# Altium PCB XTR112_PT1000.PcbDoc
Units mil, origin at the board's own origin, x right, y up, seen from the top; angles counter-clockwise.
Board outline 2104 x 1160 mil, 2 copper layers (Top Layer, Bottom Layer); 29 components, 24 nets, 75 pads, 33 vias.
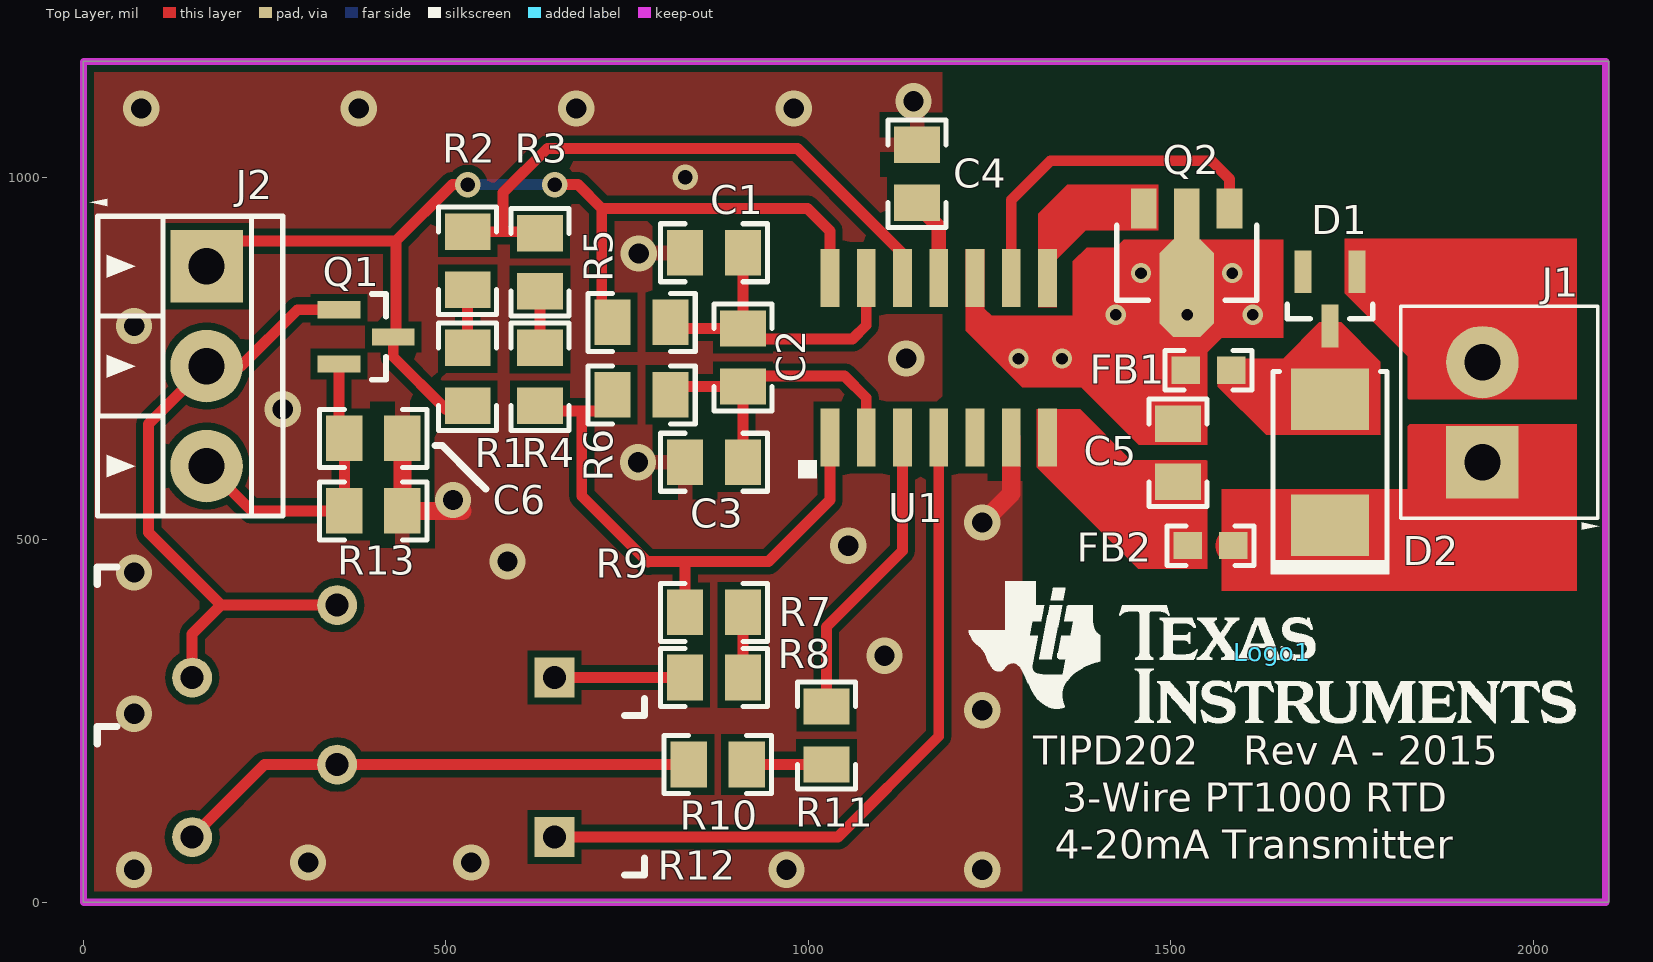
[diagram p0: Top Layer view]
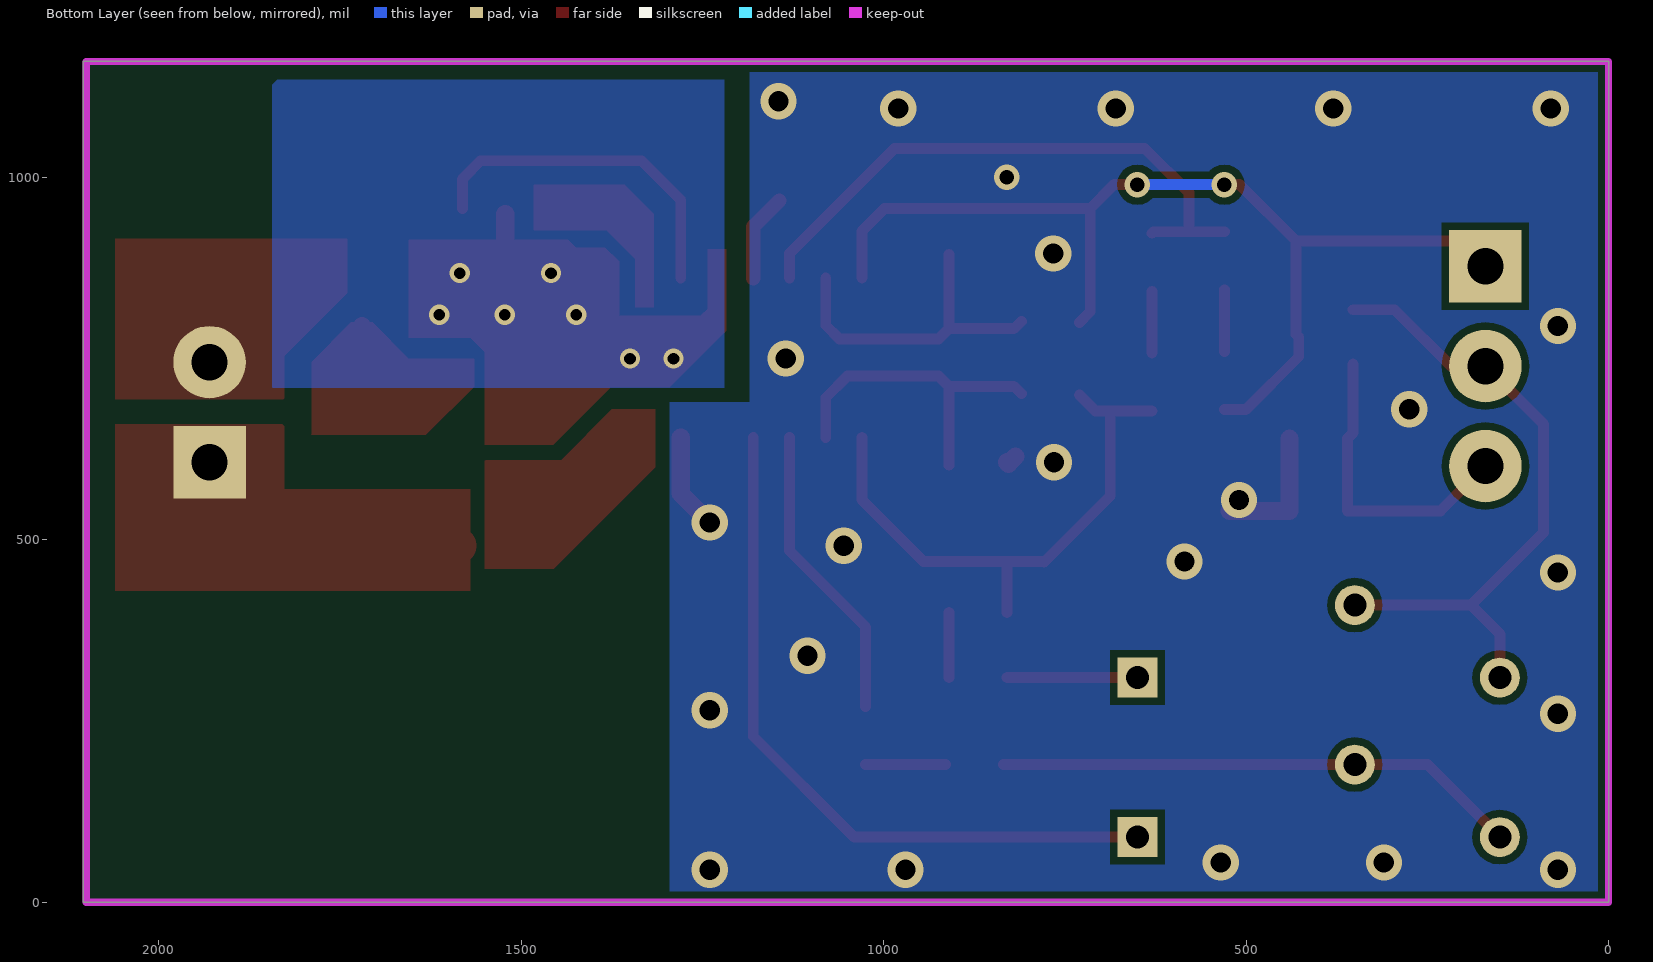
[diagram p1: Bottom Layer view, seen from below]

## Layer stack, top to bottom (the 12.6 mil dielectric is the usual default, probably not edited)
Top Solder: solder mask 0.4, Solder Resist, Dk 3.5
Top Layer: signal copper 1.4
Dielectric1: core 12.6, FR-4, Dk 4.8
Bottom Layer: signal copper 1.4
Bottom Solder: solder mask 0.4, Solder Resist, Dk 3.5

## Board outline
0,0 0,1160 2104,1160 2104,0

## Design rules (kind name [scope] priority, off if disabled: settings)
Clearance PolygonPad [Inpolygon vs IsPad] p1: gap=10
Clearance Polygon [Inpolygon] p2: gap=10
Clearance [All] p3: gap=10
FabricationTestPointUsage TestPointUsage [All] p1: valid=0 allowmultiple=FALSE
FabricationTestpoint Testpoint [All] p1: side=3 testpointundercomponent=TRUE minsize=40 maxsize=100 preferedsize=60 minholesize=0 maxholesize=40 preferedholesize=32 testpointgrid=1 allowsidetop=TRUE allowsidebottom=TRUE usegrid=TRUE gridtolerance=0.01
HoleSize [All] p1: absolutevalues=TRUE maxlimit=250 minlimit=1 maxpercent=80.000 minpercent=20.000
PolygonConnect [(InComponentClass('All Components'))] p1: connectstyle=Relief reliefconductorwidth=20 reliefentries=4 polygonreliefangle="90 Angle" airgapwidth=20
PolygonConnect PolygonConnect_1 [All] p2: connectstyle=Direct reliefconductorwidth=15 reliefentries=4 polygonreliefangle="90 Angle" airgapwidth=20
RoutingVias [All] p1: holewidth=28 width=50 viastyle="Through Hole" minholewidth=28 minwidth=50 maxholewidth=28 maxwidth=50
SilkToSolderMaskClearance SilkscreenOverComponentPads [IsPad] p1: minsilkscreentomaskgap=10 clearancetoexposedcopper=TRUE
SolderMaskExpansion [All] p1: expansion=4
UnpouredPolygon [All] p1: allowunpoured=FALSE
Width [All] p1: maxlimit=100 minlimit=8 preferedwidth=15
25 further rules are at their usual default settings.

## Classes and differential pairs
component class Logo: Logo1

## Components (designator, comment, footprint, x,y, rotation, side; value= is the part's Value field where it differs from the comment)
C1 "C2012C0G1H103J" 0805_HV 870,896 r0 top
C2 "GRM21BR71H224KA01L" 0805_HV 910,751.48 r270 top
C3 "C2012C0G1H103J" 0805_HV 870,607 r0 top
C4 "08055C104KAT2A" 0805_HV 1150,1005 r270 top
C5 "GRM216R71H103KA01D" 0805_HV 1510,620 r270 top
C6 "GRM216R71H103KA01D" 0805_HV 400,640 r0 top
D1 "BAS70-7-F" SOT-23 1719.56,832.48 r270 top
D2 "SMBJ40CA-13-F" SMB 1719.56,607 r90 top
FB1 "Used in BOM report" 0603 1552,733.95 r0 top
FB2 "Used in BOM report" 0603 1555,492 r0 top
J1 "ED555/2DS" TERM_BLK_ED555-2DS 1930,607 r90 top
J2 "ED555/3DS" TERM_BLK_ED555-3DS 170,877.4 r270 top
Logo1 "Texas Instruments" TI_Stacked_Overlay_Small 1640,345 r0 top
Q1 "BC847CLT1G" SOT-23 390,780 r0 top
Q2 "FCX690BTA" SOT-89-3 1522,882.48 r270 top
R1 "RG2012P-121-B-T5" 0805_HV 530,725 r90 top
R2 "RT0805BRD0734KL" 0805_HV 530,885 r90 top
R3 "RT0805BRD07536RL" 0805_HV 630,882.91 r270 top
R4 "RT0805BRD0759KL" 0805_HV 630,725 r270 top
R5 "CRCW080510K0FKEA" 0805_HV 770,800 r0 top
R6 "CRCW080510K0FKEA" 0805_HV 770,700 r0 top
R7 "RT0805BRD0716RL" 0805_HV 870,400 r180 top
R8 "RT0805BRD07787RL" 0805_HV 870,310 r0 top
R9 "3006P-1-500LF" BOURNS_3006P 400,360 r180 top
R10 "RT0805BRD07715RL" 0805_HV 875,190 r0 top
R11 "RT0805BRD0729R4L" 0805_HV 1025,230 r90 top
R12 "3006P-1-500LF" BOURNS_3006P 400,140 r180 top
R13 "CRCW08053K30JNEA" 0805_HV 400,540 r180 top
U1 "XTR112/14U" SO14 1180,750.94 r90 top

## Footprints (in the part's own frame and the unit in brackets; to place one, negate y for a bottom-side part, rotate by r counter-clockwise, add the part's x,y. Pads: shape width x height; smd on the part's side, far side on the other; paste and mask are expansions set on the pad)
0603 [mm] "0603 from SM-752 data"
  rect 1x0.95 smd: 1(-0.8,0) 2(0.8,0)
  silkscreen extent -1.52,-0.69 1.52,0.69, body extent -0.87,-0.47 0.87,0.47, height 0.85
0805_HV [mil] "0805 with 30mil clearance between pads"
  rect 50x63 smd: 1(-40,0) 2(40,0)
  silkscreen extent -74,-40 74,40, body extent -43,-29 43,29, height 43
BOURNS_3006P [mil] "Bourns"
  rect 55x55 hole 32: 1(-250,50)
  round 55 hole 32: 2(50,-50) 3(250,50)
  silkscreen extent -374,-102 381,102, body extent -368,-98 436,98, height 260
SMB [mil] "Molded Diode, 2-Leads, Body 5.4x3.6mm, IPC Medium Density, based on OnSemi component dimensions"
  rect 85x107.99 smd: 1(-87.01,0) 2(87.01,0)
  silkscreen extent -155,-82 125,82, body extent -106,-71 106,71, height 91
SO14 [mil]
  rect 80x26 smd: 1(-110,150) 2(-110,100) 3(-110,50) 4(-110,0) 5(-110,-50) 6(-110,-100) 7(-110,-150) 8(110,-150) 9(110,-100) 10(110,-50) 11(110,0) 12(110,50) 13(110,100) 14(110,150)
  silkscreen extent -166,169 -141,194
SOT-23 [mm] "SOT23, 3-Leads, Body 2.9x1.3mm, Pitch 0.95mm, Lead Span 2.5mm, IPC Medium Density"
  rect 1.5x0.6 smd: 1(-0.95,0.95) 2(-0.95,-0.95) 3(0.95,0)
  silkscreen extent 0.2,-1.5 0.7,1.5, body extent -1.16,-1.45 1.21,1.45, height 1
SOT-89-3 [mm] "SOT, 3-Leads, Body 4.6 x 2.6 mm, Pitch 1.5mm"
  rect 1.4x0.9 smd: 1(-1.9,1.5) 3(-1.9,-1.5)
  rect 1.8x0.9 smd: 2(-1.7,0)
  oct 3.4x1.9 smd: 4(0.9,0)
  silkscreen extent -1.3,-2.45 1.33,2.45, body extent -2.42,-2.28 1.83,2.32, height 1.62
TERM_BLK_ED555-2DS [mil]
  rect 100x100 hole 50: 1(0,0)
  round 100 hole 50: 2(138,0)
  silkscreen extent -93,-161 215,113, body extent -69,-150 207,106, height 323
TERM_BLK_ED555-3DS [mm]
  rect 2.54x2.54 hole 1.27: 1(0,0)
  round 2.54 hole 1.27: 2(3.5,0) 3(7,0)
  silkscreen extent -2.36,-4.09 8.75,2.67, body extent -1.75,-3.83 8.75,2.67, height 8.2
TI_Stacked_Overlay_Small [mil]
  silkscreen extent -418,-98 418,98

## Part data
C1 C3: "CAP, CERM, 0.01uF, 50V, +/-5%, C0G/NP0, 0805"
C2: "CAP, CERM, 0.22uF, 50V, +/-10%, X7R, 0805"
C4: "CAP, CERM, 0.1uF, 50V, +/-10%, X7R, 0805"
C5 C6: "CAP, CERM, 0.01uF, 50V, +/-10%, X7R, 0805"
D1: "Diode, Schottky, 70V, 0.07A, SOT-23"
D2: "Diode, TVS, Bi, 40V, 600W, SMB"
FB1 FB2: library part Ferrite_Bead, "300mA Ferrite Bead, 600 ohm @ 100MHz"
J1: "Terminal Block, 6A, 3.5mm Pitch, 2-Pos, TH"
J2: "Terminal Block, 6A, 3.5mm Pitch, 3-Pos, TH"
Logo1: library part TI_Logo, "Texas Instrument Corporate Signature"
Q1: library part "BC847CLT1G, ON Semiconductor", "Transistor, NPN, 45V, 0.1A, SOT-23"
Q2: library part "FCX690BTA, Diodes Inc.", "Transistor, NPN, 45V, 1A, SOT-89"
R1: "RES, 120, 0.1%, 0.125 W, 0805"
R2: "RES, 34.0 k, 0.1%, 0.125 W, 0805"
R3: "RES, 536, 0.1%, 0.125 W, 0805"
R4: "RES, 59.0 k, 0.1%, 0.125 W, 0805"
R5 R6: "RES, 10.0k ohm, 1%, 0.125W, 0805"
R7: "RES, 16.0, 0.1%, 0.125 W, 0805"
R8: "RES, 787 ohm, 0.1%, 0.125W, 0805"
R9 R12: "TRIMMER, 10K, 0.75W, TH"
R10: "RES, 715, 0.1%, 0.125 W, 0805"
R11: "RES, 29.4, 0.1%, 0.125 W, 0805"
R13: "RES, 3.3 k, 5%, 0.125 W, 0805"
U1: "IC, 4-20mA Current Transmitter with Sensor Excitation and Linearization"

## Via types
v1: diameter 50, hole 28, Top Layer to Bottom Layer, 23 vias
v2: diameter 28, hole 16, Top Layer to Bottom Layer, 7 vias
v3: diameter 35, hole 20, Top Layer to Bottom Layer, 3 vias

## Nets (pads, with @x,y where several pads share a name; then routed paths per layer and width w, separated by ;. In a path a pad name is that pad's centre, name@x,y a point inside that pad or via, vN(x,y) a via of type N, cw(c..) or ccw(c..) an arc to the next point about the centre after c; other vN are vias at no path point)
GND: C1.1 C3.1 C4.1 C6.2 R13.1 U1.6 | length 333.5
  Top Layer w25: C6.2 R13.1 v1@523,540 ; C3.1@818,615 828,605 C3.1 ; v1(1240,524) 1280,564 U1.6
  other v1: 70,45 970,45 1240,45 310,55 535,55 70,260 1240,265 1105,340 70,455 585,470 1055,492 510,555 765,607 275.19,680 1135,750 70,795 766,895 80,1095 380,1095 680,1095 980,1095 1145,1105
  other v3: 830,1000
NetC1_2: C1.2 C2.1 R5.2 U1.13 | length 455.5
  Top Layer w15: R5.2@810,801.48 820,791.48 C2.1 ; C1.2@910,894 C2.1 ; U1.13 1080,796 1061,777 924.48,777 C2.1
NetC2_2: C2.2 C3.2 R6.2 U1.2 | length 456.2
  Top Layer w15: R6.2@810,701.48 820,711.48 C2.2 ; C3.2@910,602.95 C2.2 ; U1.2 1080,696 1050,726 924.52,726 C2.2
NetC4_2: C4.2 U1.11 | length 122
  Top Layer w20: C4.2@1144,968 1180,932 U1.11
NetC5_1: C5.1 FB1.1 Q2.2 Q2.4 U1.10 | length 668.7
  Top Layer w25: U1.10 1230,804 1300.05,733.95 FB1.1 1510,723.45 C5.1 ; FB1.1@1522,735.45 Q2.4 Q2.2
  other v2: 1290,750 1350,750 1424,810.58 1522.62,810.58 1613.17,810.58 1459,868 1585,868
NetC5_2: C5.2 FB2.1 U1.7 | length 348.8
  Top Layer w30: U1.7 1478.94,492 FB2.1 1510,505.5 C5.2
NetC6_1: C6.1 J2.3 Q1.2 R13.2 | length 421.3
  Top Layer w15: J2.3 231.81,540 R13.2 C6.1 352.6,647.4 Q1.2
NetD1_1: D1.1 J1.2 | length 158.5
  Top Layer w50: 1854.08,869.88 1940,783.95 J1.2@1940,747
NetD1_3: D1.3 D2.2 FB1.2 | length 270.6
  Top Layer w25: FB1.2 1623.44,694.01 D2.2 ; D2.2@1719.56,677.04 D2.2 ; D1.3 D2.2
NetD2_1: D2.1 FB2.2 J1.1 | length 402
  Top Layer w50: FB2.2 1708.53,492 1719.56,503.03 1834.03,503.03 J1.1@1940,609
NetJ2_1: J2.1 Q1.3 R1.1 R5.1 U1.14 | length 1499.1
  Top Layer w15: J2.1 204.6,912 431,912 ; Q1.3 427.4,752.6 500,680 R1.1@530,680 ; Q1.3@431,783.6 431,912 ; v3(530,990) 509,990 431,912 ; v3(650,990) 682.28,990 715,957.28 ; R5.1 715,815 715,957.28 ; U1.14 1030,926 998.72,957.28 715,957.28
  Bottom Layer w15: J2.1 J2.1@204.6,912 ; v3(530,990) v3(650,990)
NetJ2_2: J2.2 Q1.1 R9.2 R9.3 | length 895.6
  Top Layer w15: R9.3 150,370 190,410 ; R9.2 190,410 ; Q1.1 295.4,817.4 217.61,739.61 J2.2 90,659.61 90,510 190,410
NetQ2_1: Q2.1 U1.9 | length 482.5
  Top Layer w15: U1.9 1280,969 1334,1023 1556,1023 1581.06,997.94 Q2.1
NetQ2_3: Q2.3 U1.8 | length 195.1
  Top Layer w25: U1.8 1330,899 1388.28,957.28 Q2.3
NetR1_2: R1.2 R2.1 | length 85
  Top Layer w15: R1.2@530,760 R2.1
NetR2_2: R2.2 R3.1 U1.12 | length 825.3
  Top Layer w15: R2.2 578.95,925 ; R3.1 627.91,925 578.95,925 ; U1.12 1130,895 985,1040 640,1040 578.95,978.95 578.95,925
NetR3_2: R3.2 R4.1 | length 85
  Top Layer w15: R4.1@630,757.91 R3.2
NetR4_2: R4.2 R6.1 R7.2 U1.1 | length 799.6
  Top Layer w15: R4.2@630,677.91 685,677.91 ; R6.1 707.91,677.91 685,677.91 ; R7.2 830,470 ; U1.1 1030,555 945,470 830,470 ; 685,677.91 687.5,675.41 687.5,560.5 779,469 780,470 830,470
NetR7_1: R7.1 R8.2 | length 90
  Top Layer w15: R8.2 R7.1
NetR8_1: R8.1 R9.1 | length 180
  Top Layer w15: R9.1 R8.1
NetR10_1: R10.1 R12.2 R12.3 | length 726.4
  Top Layer w15: R12.3 250,190 R12.2 R10.1
NetR10_2: R10.2 R11.1 | length 110
  Top Layer w15: R10.2 R11.1
NetR11_2: R11.2 U1.3 | length 414.4
  Top Layer w15: R11.2 1025,380 1130,485 U1.3
NetR12_1: R12.1 U1.4 | length 999.5
  Top Layer w15: R12.1 1041,90 1180,229 U1.4
pads on no net: D1.2 U1.5

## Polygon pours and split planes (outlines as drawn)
GND on Top Layer "Bottom Layer-No Net 1" (solid, remove dead copper, pour order 13): 0,1160 1184.57,1160 1184.57,690 1184.7,689.87 1295,689.87 1295,0 0,0
GND on Bottom Layer "Bottom Layer-No Net" (solid, remove dead copper, pour order 12): 0,1160 1184.57,1160 1184.57,690 1295,690 1295,0 0,0 0,1160
NetC5_1 on Bottom Layer "Bottom Layer-No Net 2" (solid, pour order 10): 1220,1135 1843.43,1135 1843.43,710.66 1845,709.47 1220,709.47 1220,1135

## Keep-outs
Keep-Out Layer:
  lines w10: 0,0 0,1160 2100,1160 2100,0 0,0

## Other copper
Top Layer:
  region net NetQ2_3: 1317,821 1317,950 1357,990 1483,990 1483,927 1383,927 1343,887 1343,821
  region net NetC5_1: 1217,901 1217,788.39 1295,710.39 1376.61,710.39 1456,631 1550,631 1550,759 1570,779 1655,779 1655,914 1435,914 1424,903 1384,903 1365,884 1365,809 1253,809 1243,819 1243,901
  region net NetC5_2: 1315,680 1375,680 1445,610 1549,610 1550,609 1550,460 1455,460 1315,600
  region net NetD2_1: 1570,570 1827,570 1827,656.61 1830,659.61 2060,659.61 2060,430 1570.4,430
  region net NetD1_1: 1740,915 2060,915 2060,694.01 1827.99,694.01 1827,695 1827,753 1740,840
  region net NetD1_3: 1565,750 1655,750 1705,800 1735,800 1789.06,745.94 1789.06,645.94 1790,645 1631.48,645 1565,711.48

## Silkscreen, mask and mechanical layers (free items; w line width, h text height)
Top Overlay:
  lines w10: 555,570 540,585 495,630 ; 495,630 485,630 495,630
  text "TIPD202" at 1310,190 h40
  text "Rev A - 2015" at 1600,190 h40
  text "3-Wire PT1000 RTD" at 1350,125 h40
  text "4-20mA Transmitter" at 1340,60 h40
Top Solder:
  lines w10: 0,0 2100,0 2100,1160 0,1160 0,0
Mechanical 1:
  the board outline again, w8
